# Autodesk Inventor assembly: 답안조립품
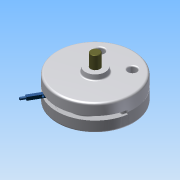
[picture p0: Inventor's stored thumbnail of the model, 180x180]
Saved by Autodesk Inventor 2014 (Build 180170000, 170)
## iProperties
Created: 2015-06
Part Number: 답안조립품
Document SubType Name: Assembly
Designer: Administrator
Author: Administrator
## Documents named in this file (10)
- C:\Documents and Settings\Administrator\바탕 화면\450631V1016\답안조립품.iam
- C:\Documents and Settings\Administrator\바탕 화면\450631V1016\본체.ipt
- C:\Documents and Settings\Administrator\바탕 화면\450631V1016\덮개.ipt
- C:\Documents and Settings\Administrator\바탕 화면\450631V1016\베어링62_22.ipt
- C:\Documents and Settings\Administrator\바탕 화면\450631V1016\축.ipt
- C:\Documents and Settings\Administrator\바탕 화면\450631V1016\멈춤링.ipt
- C:\Documents and Settings\Administrator\바탕 화면\450631V1016\슬라이더2.ipt
- C:\Documents and Settings\Administrator\바탕 화면\450631V1016\슬라이더.ipt
- C:\Documents and Settings\Administrator\바탕 화면\450631V1016\평행핀.ipt
- C:\Documents and Settings\Administrator\바탕 화면\450631V1016\M10x35.ipt
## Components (7 placed, 4 different names)
1. KS B 2023 62/22 - 22 x 50 x 14:1
2. KS B 2023 62/22 - 22 x 50 x 14:2
3. KS B 1336 22 x 1.2:1
4. KS B 1336 22 x 1.2:2
5. KS B 1320 B B 5 x  20:1
6. KS B 1003 - 미터 M 10 x 35:2
7. KS B 1003 - 미터 M 10 x 35:3
